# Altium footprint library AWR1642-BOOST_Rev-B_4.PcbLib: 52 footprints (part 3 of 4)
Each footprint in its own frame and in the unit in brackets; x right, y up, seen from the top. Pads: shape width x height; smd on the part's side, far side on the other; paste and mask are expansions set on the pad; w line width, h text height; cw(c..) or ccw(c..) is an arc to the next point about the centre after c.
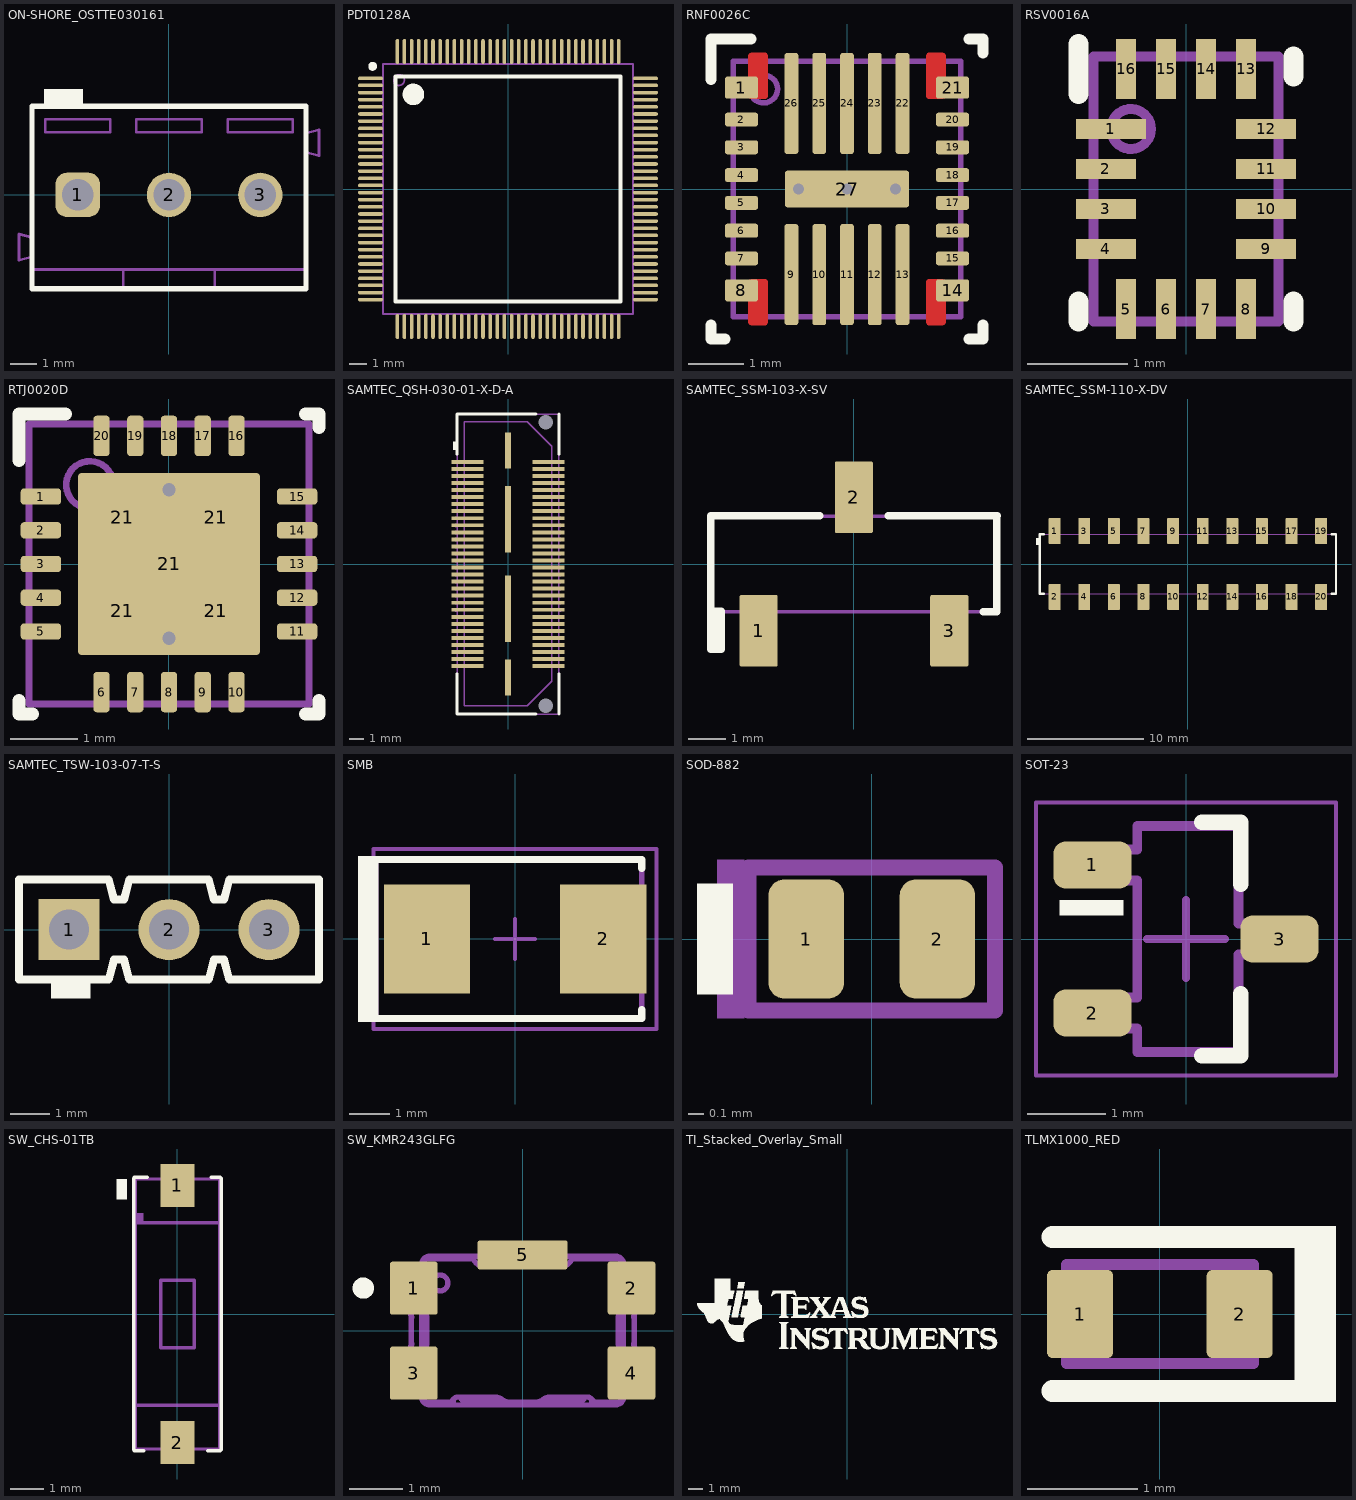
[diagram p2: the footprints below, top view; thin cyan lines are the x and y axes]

## ON-SHORE_OSTTE030161 [mm] "Terminal Block, 3.5mm, 3x1, TH"
height 8.5
pads (3):
  rrect50% 1.7x1.7 hole 1.2: 1(-3.5,0)
  round 1.7 hole 1.2: 2(0,0) 3(3.5,0)
Top Overlay:
  rectangle: -4.8,3.45 -3.3,4.05
  lines w0.2: -5.25,-3.6 -5.25,3.4 5.25,3.4 5.25,-3.6 -5.25,-3.6
Mechanical 5:
  lines w0.1: 5.25,1.634 5.75,1.5 5.75,2.5 5.25,2.366 ; -5.25,-2.859 -5.25,3.4 -1.75,3.4 1.75,3.4 5.25,3.4 5.25,-2.859 ; -5.25,-2.859 -5.25,-3.6 -1.75,-3.6 ; -5.25,-2.859 -1.75,-2.859 ; -1.75,-3.6 1.75,-3.6 ; -1.75,-3.6 -1.75,-2.859 ; -1.75,-3.6 -1.75,-2.859 ; -1.75,-2.859 1.75,-2.859 ; 1.75,-3.6 5.25,-3.6 5.25,-2.859 ; 1.75,-3.6 1.75,-2.859 ; 1.75,-3.6 1.75,-2.859 ; 1.75,-2.859 5.25,-2.859 ; -5.75,-2.5 -5.25,-2.366 -5.25,-1.634 -5.75,-1.5 -5.75,-2.5 ; -4.75,2.4 -4.75,2.9 -2.25,2.9 -2.25,2.4 -4.75,2.4 ; -1.25,2.4 -1.25,2.9 1.25,2.9 1.25,2.4 -1.25,2.4 ; 2.25,2.4 2.25,2.9 4.75,2.9 4.75,2.4 2.25,2.4
  text ".Designator" at -1.185,0.755 h1.85
3D body: height 8.4, standoff -3.8, extent -5.75,-3.6 5.75,3.4

## PDT0128A [mm] "Thin QFP, 128-Leads, Body 14x14mm, Pitch 0.4mm"
height 1.2
pads (128):
  oval 1.4x0.2 smd: 1(-7.7,6.2) 2(-7.7,5.8) 3(-7.7,5.4) 4(-7.7,5) 5(-7.7,4.6) 6(-7.7,4.2) 7(-7.7,3.8) 8(-7.7,3.4) 9(-7.7,3) 10(-7.7,2.6) 11(-7.7,2.2) 12(-7.7,1.8) 13(-7.7,1.4) 14(-7.7,1) 15(-7.7,0.6) 16(-7.7,0.2) 17(-7.7,-0.2) 18(-7.7,-0.6) 19(-7.7,-1) 20(-7.7,-1.4) 21(-7.7,-1.8) 22(-7.7,-2.2) 23(-7.7,-2.6) 24(-7.7,-3) 25(-7.7,-3.4) 26(-7.7,-3.8) 27(-7.7,-4.2) 28(-7.7,-4.6) 29(-7.7,-5) 30(-7.7,-5.4) 31(-7.7,-5.8) 32(-7.7,-6.2) 65(7.7,-6.2) 66(7.7,-5.8) 67(7.7,-5.4) 68(7.7,-5) 69(7.7,-4.6) 70(7.7,-4.2) 71(7.7,-3.8) 72(7.7,-3.4) 73(7.7,-3) 74(7.7,-2.6) 75(7.7,-2.2) 76(7.7,-1.8) 77(7.7,-1.4) 78(7.7,-1) 79(7.7,-0.6) 80(7.7,-0.2) 81(7.7,0.2) 82(7.7,0.6) 83(7.7,1) 84(7.7,1.4) 85(7.7,1.8) 86(7.7,2.2) 87(7.7,2.6) 88(7.7,3) 89(7.7,3.4) 90(7.7,3.8) 91(7.7,4.2) 92(7.7,4.6) 93(7.7,5) 94(7.7,5.4) 95(7.7,5.8) 96(7.7,6.2)
  oval 0.2x1.4 smd: 33(-6.2,-7.7) 34(-5.8,-7.7) 35(-5.4,-7.7) 36(-5,-7.7) 37(-4.6,-7.7) 38(-4.2,-7.7) 39(-3.8,-7.7) 40(-3.4,-7.7) 41(-3,-7.7) 42(-2.6,-7.7) 43(-2.2,-7.7) 44(-1.8,-7.7) 45(-1.4,-7.7) 46(-1,-7.7) 47(-0.6,-7.7) 48(-0.2,-7.7) 49(0.2,-7.7) 50(0.6,-7.7) 51(1,-7.7) 52(1.4,-7.7) 53(1.8,-7.7) 54(2.2,-7.7) 55(2.6,-7.7) 56(3,-7.7) 57(3.4,-7.7) 58(3.8,-7.7) 59(4.2,-7.7) 60(4.6,-7.7) 61(5,-7.7) 62(5.4,-7.7) 63(5.8,-7.7) 64(6.2,-7.7) 97(6.2,7.7) 98(5.8,7.7) 99(5.4,7.7) 100(5,7.7) 101(4.6,7.7) 102(4.2,7.7) 103(3.8,7.7) 104(3.4,7.7) 105(3,7.7) 106(2.6,7.7) 107(2.2,7.7) 108(1.8,7.7) 109(1.4,7.7) 110(1,7.7) 111(0.6,7.7) 112(0.2,7.7) 113(-0.2,7.7) 114(-0.6,7.7) 115(-1,7.7) 116(-1.4,7.7) 117(-1.8,7.7) 118(-2.2,7.7) 119(-2.6,7.7) 120(-3,7.7) 121(-3.4,7.7) 122(-3.8,7.7) 123(-4.2,7.7) 124(-4.6,7.7) 125(-5,7.7) 126(-5.4,7.7) 127(-5.8,7.7) 128(-6.2,7.7)
Top Overlay:
  circle w0.25: c-7.575,6.87 r0.125
  circle w0.6: c-5.3,5.3 r0.3
  lines w0.2: -6.3,-6.3 -6.3,6.3 6.3,6.3 6.3,-6.3 -6.3,-6.3
Mechanical 5:
  circle w0.1: c-6.1,6.1 r0.3
  lines w0.1: -7,-7 -7,7 7,7 7,-7 -7,-7
  text ".Designator" at 0.191,-1.08 h1.02
3D body: height 1.07, standoff 0, extent -8,-8 8,8

## RNF0026C [mm] "QFN, 26-Leads, Body 4x4.5mm, Pitch 0.5mm"
height 0.9
pads (57):
  rrect25% 0.6x0.4 smd paste-0.3: 1(-1.9,1.825) 8(-1.9,-1.825) 14(1.9,-1.825) 21(1.9,1.825)
  rrect40% 0.6x0.25 smd paste+0: 2(-1.9,1.25) 3(-1.9,0.75) 4(-1.9,0.25) 5(-1.9,-0.25) 6(-1.9,-0.75) 7(-1.9,-1.25) 15(1.9,-1.25) 16(1.9,-0.75) 17(1.9,-0.25) 18(1.9,0.25) 19(1.9,0.75) 20(1.9,1.25)
  rrect40% 0.25x1.82 smd paste-1: 9(-1,-1.54) 10(-0.5,-1.54) 11(0,-1.54) 12(0.5,-1.54) 13(1,-1.54) 22(1,1.54) 23(0.5,1.54) 24(0,1.54) 25(-0.5,1.54) 26(-1,1.54)
  rrect15% 2.24x0.66 smd paste-1: 27(0,0)
  rrect50% 0.6x0.3 on Top Paste: ""(-1.9,-1.775) ""(-1.9,1.775) ""(1.9,-1.775) ""(1.9,1.775)
  rrect50% 0.3x0.825 on Top Paste: ""(-1.575,-2.037) ""(-1.575,2.037) ""(1.575,-2.037) ""(1.575,2.037)
  rrect50% 0.25x0.81 on Top Paste: ""(-1,-2.045) ""(-1,-1.035) ""(-1,1.035) ""(-1,2.045) ""(-0.5,-2.045) ""(-0.5,-1.035) ""(-0.5,1.035) ""(-0.5,2.045) ""(0,-2.045) ""(0,-1.035) ""(0,1.035) ""(0,2.045) ""(0.5,-2.045) ""(0.5,-1.035) ""(0.5,1.035) ""(0.5,2.045) ""(1,-2.045) ""(1,-1.035) ""(1,1.035) ""(1,2.045)
  rrect50% 0.98x0.66 on Top Paste: ""(-0.59,0) ""(0.59,0)
via -0.87,0 diameter 0.5 hole 0.2
via 0,0 diameter 0.5 hole 0.2
via 0.87,0 diameter 0.5 hole 0.2
Top Layer:
  region: -1.775,1.675 -1.775,2.4 -1.775,2.41 -1.767,2.428 -1.753,2.442 -1.735,2.45 -1.725,2.45 -1.475,2.45 -1.465,2.45 -1.447,2.442 -1.433,2.428 -1.425,2.41 -1.425,2.4 -1.425,1.675 -1.425,1.665 -1.433,1.647 -1.447,1.633 -1.465,1.625 -1.475,1.625 -1.725,1.625 -1.735,1.625 -1.753,1.633 -1.767,1.647 -1.775,1.665
  region: 1.425,1.675 1.425,2.4 1.425,2.41 1.433,2.428 1.447,2.442 1.465,2.45 1.475,2.45 1.725,2.45 1.735,2.45 1.753,2.442 1.767,2.428 1.775,2.41 1.775,2.4 1.775,1.675 1.775,1.665 1.767,1.647 1.753,1.633 1.735,1.625 1.725,1.625 1.475,1.625 1.465,1.625 1.447,1.633 1.433,1.647 1.425,1.665
  region: 1.425,-2.4 1.425,-1.675 1.425,-1.665 1.433,-1.647 1.447,-1.633 1.465,-1.625 1.475,-1.625 1.725,-1.625 1.735,-1.625 1.753,-1.633 1.767,-1.647 1.775,-1.665 1.775,-1.675 1.775,-2.4 1.775,-2.41 1.767,-2.428 1.753,-2.442 1.735,-2.45 1.725,-2.45 1.475,-2.45 1.465,-2.45 1.447,-2.442 1.433,-2.428 1.425,-2.41
  region: -1.775,-2.4 -1.775,-1.675 -1.775,-1.665 -1.767,-1.647 -1.753,-1.633 -1.735,-1.625 -1.725,-1.625 -1.475,-1.625 -1.465,-1.625 -1.447,-1.633 -1.433,-1.647 -1.425,-1.665 -1.425,-1.675 -1.425,-2.4 -1.425,-2.41 -1.433,-2.428 -1.447,-2.442 -1.465,-2.45 -1.475,-2.45 -1.725,-2.45 -1.735,-2.45 -1.753,-2.442 -1.767,-2.428 -1.775,-2.41
Top Overlay:
  lines w0.2: -2.45,-2.45 -2.45,-2.7 -2.2,-2.7 ; -2.45,1.975 -2.45,2.7 -1.725,2.7 ; 2.2,-2.7 2.45,-2.7 2.45,-2.45 ; 2.2,2.7 2.45,2.7 2.45,2.45
Mechanical 5:
  circle w0.1: c-1.5,1.8 r0.25
  lines w0.1: -2.05,-2.3 2.05,-2.3 2.05,2.3 -2.05,2.3 -2.05,-2.3
  text ".Designator" at 0.894,0.399 h0.9
3D body: height 0.9, standoff 0.9, extent -1.749,1.551 -1.251,2.049
3D body: height 0.9, standoff 0, extent -2,-2.25 2,2.25

## RSV0016A [mm] "QFN, 16-Leads, Body 1.8x2.6mm, Pitch 0.4mm, TI Recommended"
height 0.55
pads (16):
  rect 0.7x0.2 smd: 1(-0.75,0.6)
  rect 0.6x0.2 smd: 2(-0.8,0.2) 3(-0.8,-0.2) 4(-0.8,-0.6) 9(0.8,-0.6) 10(0.8,-0.2) 11(0.8,0.2) 12(0.8,0.6)
  rect 0.2x0.6 smd: 5(-0.6,-1.2) 6(-0.2,-1.2) 7(0.2,-1.2) 8(0.6,-1.2) 13(0.6,1.2) 14(0.2,1.2) 15(-0.2,1.2) 16(-0.6,1.2)
Top Overlay:
  lines w0.2: -1.075,-1.325 -1.075,-1.125 ; -1.075,0.95 -1.075,1.45 ; 1.075,-1.325 1.075,-1.125 ; 1.075,1.125 1.075,1.325
Mechanical 5:
  circle w0.1: c-0.55,0.6 r0.2
  lines w0.1: -0.925,-1.325 -0.925,1.325 0.925,1.325 0.925,-1.325 -0.925,-1.325
  text ".Designator" at 0.252,0.774 h0.38
3D body: height 0.55, standoff 0, extent -0.925,-1.325 0.925,1.325
3D body: height 0.56, standoff 0.4, extent -0.749,0.401 -0.351,0.799

## RTJ0020D [mm] "QFN, 20-Leads, Body 4x4mm, Pitch 0.5mm, Thermal Pad 2.7x2.7mm, TI Recommended"
height 0.8
pads (25):
  rrect42% 0.6x0.24 smd: 1(-1.9,1) 2(-1.9,0.5) 3(-1.9,0) 4(-1.9,-0.5) 5(-1.9,-1) 11(1.9,-1) 12(1.9,-0.5) 13(1.9,0) 14(1.9,0.5) 15(1.9,1)
  rrect42% 0.24x0.6 smd: 6(-1,-1.9) 7(-0.5,-1.9) 8(0,-1.9) 9(0.5,-1.9) 10(1,-1.9) 16(1,1.9) 17(0.5,1.9) 18(0,1.9) 19(-0.5,1.9) 20(-1,1.9)
  rrect50% 1.19x1.19 on Top Paste: 21(-0.695,-0.695) 21(-0.695,0.695) 21(0.695,-0.695) 21(0.695,0.695)
  rrect4% 2.7x2.7 smd paste-1.4: 21(0,0)
via 0,-1.1 diameter 0.5 hole 0.2
via 0,1.1 diameter 0.5 hole 0.2
Top Overlay:
  lines w0.2: -2.225,-2.025 -2.225,-2.225 -2.025,-2.225 ; -2.225,1.54 -2.225,2.225 -1.54,2.225 ; 2.025,-2.225 2.225,-2.225 2.225,-2.025 ; 2.025,2.225 2.225,2.225 2.225,2.025
Mechanical 5:
  circle w0.1: c-1.175,1.175 r0.35
  lines w0.1: -2.075,-2.075 2.075,-2.075 2.075,2.075 -2.075,2.075 -2.075,-2.075
  text ".Designator" at 0.696,0.566 h1.85
3D body: height 0.8, standoff 0, extent -2.075,-2.075 2.075,2.075
3D body: height 0.8, standoff 0.5, extent -1.524,0.826 -0.826,1.524

## SAMTEC_QSH-030-01-X-D-A [mm] "Receptacle, 0.5 mm, 30x2, TH"
height 3.327
pads (66):
  rect 2.27x0.279 smd: 1(-2.865,7.25) 2(2.865,7.25) 3(-2.865,6.75) 4(2.865,6.75) 5(-2.865,6.25) 6(2.865,6.25) 7(-2.865,5.75) 8(2.865,5.75) 9(-2.865,5.25) 10(2.865,5.25) 11(-2.865,4.75) 12(2.865,4.75) 13(-2.865,4.25) 14(2.865,4.25) 15(-2.865,3.75) 16(2.865,3.75) 17(-2.865,3.25) 18(2.865,3.25) 19(-2.865,2.75) 20(2.865,2.75) 21(-2.865,2.25) 22(2.865,2.25) 23(-2.865,1.75) 24(2.865,1.75) 25(-2.865,1.25) 26(2.865,1.25) 27(-2.865,0.75) 28(2.865,0.75) 29(-2.865,0.25) 30(2.865,0.25) 31(-2.865,-0.25) 32(2.865,-0.25) 33(-2.865,-0.75) 34(2.865,-0.75) 35(-2.865,-1.25) 36(2.865,-1.25) 37(-2.865,-1.75) 38(2.865,-1.75) 39(-2.865,-2.25) 40(2.865,-2.25) 41(-2.865,-2.75) 42(2.865,-2.75) 43(-2.865,-3.25) 44(2.865,-3.25) 45(-2.865,-3.75) 46(2.865,-3.75) 47(-2.865,-4.25) 48(2.865,-4.25) 49(-2.865,-4.75) 50(2.865,-4.75) 51(-2.865,-5.25) 52(2.865,-5.25) 53(-2.865,-5.75) 54(2.865,-5.75) 55(-2.865,-6.25) 56(2.865,-6.25) 57(-2.865,-6.75) 58(2.865,-6.75) 59(-2.865,-7.25) 60(2.865,-7.25)
  round 0 hole 1.02 unplated mask+0.127: MH1(2.67,10.065) MH2(2.67,-10.065)
  rect 0.43x2.54 smd: MP1(0,8.065) MP4(0,-8.065)
  rect 0.43x4.7 smd: MP2(0,3.175) MP3(0,-3.175)
Top Overlay:
  rectangle: -3.9,8.1 -3.62,8.7
  lines w0.2: -3.62,-7.789 -3.62,-10.655 2,-10.655 ; -3.62,7.789 -3.62,10.655 2,10.655 ; 3.62,-10.655 3.62,-7.789 ; 3.62,7.789 3.62,10.655
Mechanical 5:
  drawing of 190 lines, arcs and shapes, not listed
  text ".Designator" at -1.429,-0.579 h1.02
3D body: height 3.25, standoff -0.75, extent -3.746,-10.636 3.747,10.674

## SAMTEC_SSM-103-X-SV [mm] "Receptacle, 2.54mm, 3x1, SMT"
height 7.541
pads (3):
  rrect10% 1.02x1.905 smd: 1(-2.54,-1.777) 2(0,1.777) 3(2.54,-1.777)
Top Overlay:
  region: -3.53,-2.275 -3.53,-1.256 -3.81,-1.256 -3.81,-2.275
  lines w0.2: -0.91,1.284 -3.81,1.284 -3.81,-1.256 ; 0.91,1.284 3.81,1.284 ; 3.45,-1.27 3.81,-1.27 3.81,1.27 ; -3.81,-1.256 -3.53,-1.256 -3.53,-2.275 -3.81,-2.275 -3.81,-1.256
Mechanical 5:
  lines w0.1: -2.794,-1.27 -2.794,-2.286 -2.286,-2.286 -2.286,-1.27 ; -0.254,1.27 -0.254,2.286 0.254,2.286 0.254,1.27 ; 2.286,-1.27 2.286,-2.286 2.794,-2.286 2.794,-1.27 ; -3.81,-1.27 -3.81,1.27 3.81,1.27 3.81,-1.27 -3.81,-1.27
  text ".Designator" at 1.064,0.752 h1.02
3D body: height 7.51, standoff 0.01, extent -3.81,-2.286 3.81,2.286

## SAMTEC_SSM-110-X-DV [mm] "Receptacle, 2.54mm, 10x2, SMT"
height 7.47
pads (20):
  rrect10% 1.02x2.22 smd: 1(-11.43,2.825) 2(-11.43,-2.825) 3(-8.89,2.825) 4(-8.89,-2.825) 5(-6.35,2.825) 6(-6.35,-2.825) 7(-3.81,2.825) 8(-3.81,-2.825) 9(-1.27,2.825) 10(-1.27,-2.825) 11(1.27,2.825) 12(1.27,-2.825) 13(3.81,2.825) 14(3.81,-2.825) 15(6.35,2.825) 16(6.35,-2.825) 17(8.89,2.825) 18(8.89,-2.825) 19(11.43,2.825) 20(11.43,-2.825)
Top Overlay:
  rectangle: -13.025,1.625 -12.675,2.225
  lines w0.2: -12.34,-2.54 -12.7,-2.54 -12.7,2.54 -12.34,2.54 ; 12.34,-2.54 12.7,-2.54 12.7,2.54 12.34,2.54
Mechanical 5:
  lines w0.1: -11.684,-2.54 -11.684,-3.518 -11.176,-3.518 -11.176,-2.54 ; -11.684,2.54 -11.684,3.518 -11.176,3.518 -11.176,2.54 ; -9.144,-2.54 -9.144,-3.518 -8.636,-3.518 -8.636,-2.54 ; -9.144,2.54 -9.144,3.518 -8.636,3.518 -8.636,2.54 ; -6.604,-2.54 -6.604,-3.518 -6.096,-3.518 -6.096,-2.54 ; -6.604,2.54 -6.604,3.518 -6.096,3.518 -6.096,2.54 ; -4.064,-2.54 -4.064,-3.518 -3.556,-3.518 -3.556,-2.54 ; -4.064,2.54 -4.064,3.518 -3.556,3.518 -3.556,2.54 ; -1.524,-2.54 -1.524,-3.518 -1.016,-3.518 -1.016,-2.54 ; -1.524,2.54 -1.524,3.518 -1.016,3.518 -1.016,2.54 ; 1.016,-2.54 1.016,-3.518 1.524,-3.518 1.524,-2.54 ; 1.016,2.54 1.016,3.518 1.524,3.518 1.524,2.54 ; 3.556,-2.54 3.556,-3.518 4.064,-3.518 4.064,-2.54 ; 3.556,2.54 3.556,3.518 4.064,3.518 4.064,2.54 ; 6.096,-2.54 6.096,-3.518 6.604,-3.518 6.604,-2.54 ; 6.096,2.54 6.096,3.518 6.604,3.518 6.604,2.54 ; 8.636,-2.54 8.636,-3.518 9.144,-3.518 9.144,-2.54 ; 8.636,2.54 8.636,3.518 9.144,3.518 9.144,2.54 ; 11.176,-2.54 11.176,-3.518 11.684,-3.518 11.684,-2.54 ; 11.176,2.54 11.176,3.518 11.684,3.518 11.684,2.54 ; -12.7,-2.54 12.7,-2.54 12.7,2.54 -12.7,2.54 -12.7,-2.54
  text ".Designator" at -0.546,0.077 h1.02
3D body: height 7.42, standoff 0, extent -12.7,-3.518 12.7,3.518

## SAMTEC_TSW-103-07-T-S [mm] "Header, 2.54 mm, 3x1, TH"
height 8.64
pads (3):
  rect 1.55x1.55 hole 1.02: 1(-2.54,0)
  round 1.55 hole 1.02: 2(0,0) 3(2.54,0)
Top Overlay:
  rectangle: -3,-1.75 -2,-1.27
  lines w0.2: -3.81,-1.27 -1.534,-1.27 -1.397,-0.762 -1.27,-0.762 -1.143,-0.762 -1.006,-1.27 1.006,-1.27 1.143,-0.762 1.27,-0.762 1.397,-0.762 1.534,-1.27 3.81,-1.27 3.81,1.27 1.534,1.27 1.397,0.762 1.27,0.762 1.143,0.762 1.006,1.27 -1.006,1.27 -1.143,0.762 -1.27,0.762 -1.397,0.762 -1.534,1.27 -3.81,1.27 -3.81,-1.27
Mechanical 5:
  lines w0.1: -3.81,-1.27 -3.81,1.27 -1.534,1.27 -1.397,0.762 -1.27,0.762 -1.143,0.762 -1.006,1.27 1.006,1.27 1.143,0.762 1.27,0.762 1.397,0.762 1.534,1.27 3.81,1.27 3.81,-1.27 1.534,-1.27 1.397,-0.762 1.27,-0.762 1.143,-0.762 1.006,-1.27 -1.006,-1.27 -1.143,-0.762 -1.27,-0.762 -1.397,-0.762 -1.534,-1.27 -3.81,-1.27
  text ".Designator" at -4.406,-0.428 h1.02
3D body: height 8.39, standoff -2.53, extent -3.81,-1.27 3.81,1.27

## SMB [mm] "Molded Diode, 2-Leads, Body 5.4x3.6mm, IPC Medium Density, based on OnSemi component dimensions"
height 2.65
pads (2):
  rect 2.159x2.743 smd: 1(-2.21,0) 2(2.21,0)
Top Overlay:
  rectangle: -3.937,-2.083 -3.429,2.083
  lines w0.178: -3.607,-1.994 3.175,-1.994 3.175,-1.765 ; -3.607,1.994 3.175,1.994 3.175,1.765
Mechanical 5:
  rectangle: -3.937,-2.083 -3.429,2.083
  lines w0.127: -3.607,-1.994 3.175,-1.994 3.175,-1.765 3.175,1.765 3.175,1.994 -3.607,1.994
  text ".Designator" at -2.311,-0.508 h1.02
Mechanical 15:
  lines w0.1: -0.5,0 0.5,0 ; 0,-0.5 0,0.5 ; -3.55,-2.25 -3.55,2.25 3.55,2.25 3.55,-2.25 -3.55,-2.25
3D body: height 2.32, standoff 0.02, extent -2.7,-1.8 2.7,1.8

## SOD-882 [mm] "Skyworks"
height 0.5
pads (2):
  rrect42% 0.475x0.75 smd: 1(-0.412,0) 2(0.412,0)
Top Overlay:
  rectangle: -1.1,-0.35 -0.875,0.35
Mechanical 5:
  rectangle: -0.975,-0.5 -0.8,0.5
  lines w0.1: -0.775,-0.45 -0.775,0.45 0.775,0.45 0.775,-0.45 -0.775,-0.45
  text ".Designator" at -0.575,-0.15 h0.3
3D body: height 0.5, standoff 0.5, extent -0.406,-0.2 -0.3,0.2
3D body: height 0.5, standoff 0, extent -0.5,-0.3 0.5,0.3

## SOT-23 [mm] "SOT23, 3-Leads, Body 2.9x1.3mm, Pitch 0.95mm, Lead Span 2.5mm, IPC Medium Density"
height 1.1
pads (3):
  rrect50% 1x0.6 smd: 1(-1.2,0.95) 2(-1.2,-0.95) 3(1.2,0)
Top Overlay:
  rectangle: -1.625,0.3 -0.8,0.5
  lines w0.2: 0.2,-1.5 0.7,-1.5 0.7,-0.7 ; 0.2,1.5 0.7,1.5 0.7,0.7
Mechanical 5:
  lines w0.127: -1.16,-1.15 -0.625,-1.15 -0.625,-1.45 0.675,-1.45 0.675,-0.2 1.21,-0.2 1.21,0.2 0.675,0.2 0.675,1.45 -0.625,1.45 -0.625,1.15 -1.16,1.15 -1.16,0.75 -0.625,0.75 -0.625,-0.75 -1.16,-0.75 -1.16,-1.15
  text ".Designator" at -0.239,0.784 h0.64
Mechanical 15:
  lines w0.05: -1.925,-1.75 -1.925,1.75 1.925,1.75 1.925,-1.75 -1.925,-1.75
  lines w0.1: -0.5,0 0.5,0 ; 0,-0.5 0,0.5
3D body: height 1, standoff 0, extent -1.16,-1.45 1.21,1.45

## SW_CHS-01TB [mm] "CHS Recommended footprint"
height 2.5
pads (2):
  rect 1x1.27 smd: 1(0,3.81) 2(0,-3.81)
Top Overlay:
  region: -1.8,4 -1.5,4 -1.5,3.4 -1.8,3.4
  lines w0.1: -1,-4.05 -1.275,-4.05 -1.3,-4.025 -1.3,4.025 -1.275,4.05 -0.9,4.05 ; 0.9,-4.05 1.275,-4.05 1.3,-4.025 1.3,4.025 1.275,4.05 1,4.05
Mechanical 5:
  rectangle: -1.25,2.7 -1,3
  lines w0.1: -1.25,-4 1.25,-4 1.25,4 -1.25,4 -1.25,-4 ; -1.25,-2.7 1.25,-2.7 1.25,2.7 -1.25,2.7 -1.25,-2.7 ; -0.5,-1 -0.5,1 0.5,1 0.5,-1 -0.5,-1
  text ".Designator" at 1.72,3.481 h1.02
3D body: height 2.5, standoff 0, extent -1.249,-2.699 1.249,2.699
3D body: height 0.2, standoff 0, extent -0.3,2.7 0.3,4
3D body: height 0.2, standoff 0, extent -0.3,-4 0.3,-2.7
3D body: height 2.51, standoff 2.4, extent -0.3,-0.9 0.3,-0.2

## SW_KMR243GLFG [mm] "SMD, 5-Leads, Body 4.2x2.8mm"
height 1.9
pads (5):
  rrect11% 0.9x1 smd: 1(-2.05,0.8) 2(2.05,0.8) 3(-2.05,-0.8) 4(2.05,-0.8)
  rrect18% 1.7x0.55 smd: 5(0,1.425)
Top Overlay:
  circle w0.2: c-3,0.8 r0.1
Mechanical 5:
  drawing of 4459 lines, arcs and shapes, not listed
  text ".Designator" at 0.619,0.245 h1
3D body: height 1.92, standoff -0.02, extent -2.3,-1.4 2.3,1.4

## TI_Stacked_Overlay_Small [mm]
Top Overlay:
  drawing of 18 lines, arcs and shapes, not listed

## TLMX1000_RED [mm] "SMD, 2-Leads, Body 1.6x0.8mm"
height 0.65
pads (2):
  rrect17% 0.6x0.8 smd: 1(-0.725,0) 2(0.725,0)
Top Overlay:
  rectangle: 1.325,-0.8 1.6,0.8
  lines w0.2: -0.975,-0.7 1.325,-0.7 1.325,0.7 -0.975,0.7
Mechanical 5:
  rectangle: 0.6,-0.45 0.85,0.45
  lines w0.1: -0.85,-0.45 0.85,-0.45 0.85,0.45 -0.85,0.45 -0.85,-0.45
  text ".Designator" at -0.5,-0.1 h0.3
3D body: height 0.65, standoff 0, extent -0.85,-0.45 0.85,0.45
3D body: height 0.65, standoff 0.65, extent 0,-0.2 0.3,0.2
